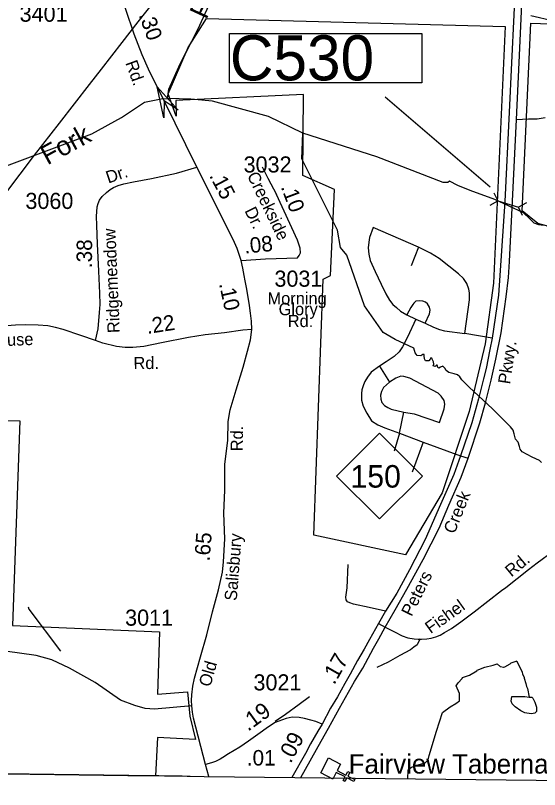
# Model space of a CAD drawing. Extents: x 1547597 to 1699558, y 810033 to 920809.
# Drawn here: x 1623103 to 1627167, y 819952 to 825959 of the extents above; entities that cross this region are included whole.
import ezdxf

# ---------------------------------------------------------------- set-up
doc = ezdxf.new("R2010")
doc.units = 0
for name, color, linetype in [('Exist Boundary Political City Limit New', 7, 'Continuous'), ('Exist Boundary Political CountyLine', 7, 'Continuous'), ('Exist Cultural Church CELL', 7, 'Continuous'), ('Exist Cultural Church Label', 7, 'Continuous'), ('Exist Hydrographic Creek Single Shore', 7, 'Continuous'), ('Exist Hydrographic Creek Single Shore Label', 7, 'Continuous'), ('Exist Hydrographic Misc Water Feature', 7, 'Continuous'), ('Exist Road Non-System Type 51', 7, 'Continuous'), ('Exist Road Primary NC Divided Attributed', 7, 'Continuous'), ('Exist Road Primary NC Label', 7, 'Continuous'), ('Exist Road Primary NC Service Mileage Hundredths English Label', 7, 'Continuous'), ('Exist Road Primary NC Shield CELL', 7, 'Continuous'), ('Exist Road Primary NC Shield Number Label', 7, 'Continuous'), ('Exist Road Primary NC Structure Culvert CELL', 7, 'Continuous'), ('Exist Road Primary NC Structure Culvert Number Label', 7, 'Continuous'), ('Exist Road Secondary Mileage Hundredths English Label', 7, 'Continuous'), ('Exist Road Secondary Structure Standard Bridge Attributed CELL', 7, 'Continuous'), ('Exist Road Secondary Type 51 Attributed', 7, 'Continuous'), ('Exist Road Secondary Type 51 Label', 7, 'Continuous'), ('Exist Road Secondary Type 51 Number Label', 7, 'Continuous'), ('Exist Utilities Electrical Transmission Line', 7, 'Continuous'), ('Map Preparation Boundary City Limit Buffer Line', 7, 'Continuous')]:
    doc.layers.add(name, color=color, linetype=linetype)

msp = doc.modelspace()

# ---------------------------------------------------------------- linework, layer by layer
at = {"layer": 'Exist Boundary Political City Limit New'}
for points in [[(1624585.1, 825934.1), (1626899.2, 825873.3), (1626810, 823882.4), (1626744.7, 823409.9), (1626621.2, 822886.4), (1626410.5, 822253.9), (1626127.2, 821774), (1625415.4, 821926.7), (1625488, 823911.5), (1625546.1, 823940.6), (1625577.9, 824608.7), (1625332.2, 824717.2), (1625335.8, 825346.1), (1624345.6, 825299.1), (1624349.2, 825176.2), (1624287.8, 825349.7), (1624443.2, 825711.2), (1624585.1, 825934.1)], [(1627100, 825900), (1628206.7, 825861), (1628172.5, 825115), (1628265.2, 825110.1), (1628245.7, 824047.1), (1627631.4, 824276.3), (1627607, 824183.6), (1627548.5, 824212.9), (1627524.2, 824247), (1627480.3, 824266.5), (1627455.9, 824271.4), (1627455.9, 824242.2), (1627441.3, 824217.8), (1627353.5, 824271.4), (1627324.3, 824266.5), (1627221.9, 824325.1), (1627153.7, 824344.6), (1627031.8, 824442.1), (1627100, 825900)], [(1622237.9, 822828.2), (1623135.5, 822813.7), (1623080, 821224.5), (1624219.3, 821176.2), (1624203.5, 820692.6), (1624436.5, 820710.6), (1624454.3, 820520.6), (1624498.1, 820339.4), (1624204.6, 820355.8), (1624188.1, 820058.9)], [(1624188.1, 820058.9), (1623982.5, 820061.2), (1621271.1, 820096.9)]]:
    msp.add_lwpolyline(points, dxfattribs=at)
at = {"layer": 'Exist Boundary Political CountyLine'}
msp.add_lwpolyline([(1606492.6, 820282.1), (1613860.9, 820194.5), (1614148.1, 820194.4), (1614278.7, 820193.7), (1614685.6, 820195), (1614832.4, 820191.9), (1615113.9, 820191.3), (1615321.1, 820189.2), (1615424.8, 820185.5), (1615839, 820171.5), (1623973.3, 820060), (1623995.2, 820060.7), (1624042.9, 820061.2), (1624114.1, 820060.5), (1624171.2, 820059.7), (1624213.4, 820059.1), (1624257.5, 820058.7), (1624364.8, 820057.3), (1624394.8, 820056.9), (1624433.9, 820056.2), (1624457.5, 820055.9), (1624566.7, 820052.4), (1633697.6, 819951.5)], dxfattribs=at)
at = {"layer": 'Exist Cultural Church CELL'}
msp.add_lwpolyline([(1625624.1, 820149.1), (1625598.1, 820098.4), (1625665.9, 820063.6), (1625680.5, 820092.1), (1625694.7, 820084.8), (1625680.1, 820056.3), (1625733.6, 820028.8), (1625726.2, 820014.6), (1625672.7, 820042), (1625658.1, 820013.6), (1625643.9, 820020.9), (1625658.5, 820049.3), (1625590.8, 820084.1), (1625564.4, 820032.9), (1625469.7, 820081.6), (1625529.4, 820197.7)], close=True, dxfattribs=at)
at = {"layer": 'Exist Hydrographic Creek Single Shore'}
for points in [[(1624282.5, 825315.4), (1624291.3, 825386.3), (1624378.8, 825583.4), (1624516.2, 825850.3), (1624895.5, 826674.4), (1624999.6, 826883.7), (1625072.7, 827054.3), (1625138.1, 827162.8), (1625227.8, 827231.5), (1625348.7, 827304.6), (1625502.5, 827438.6), (1625607.7, 827471.8), (1625689.6, 827475.1), (1625834.7, 827440.8)], [(1622087.2, 824423.2), (1622278.3, 824509.2), (1623695.3, 825040.7), (1623925.8, 825167), (1624104.2, 825285.5), (1624233.3, 825311.9), (1624282.5, 825315.4)], [(1625330.5, 825045.8), (1625066.2, 825173.5), (1624631.4, 825294.3), (1624461.9, 825309.9), (1624282.5, 825315.4)], [(1627182.1, 822488.9), (1627165.5, 822505.5), (1627110.6, 822531.5), (1627032.6, 822572.5), (1627017, 822593.5), (1627010.4, 822614.6), (1627001, 822647.8), (1626979.4, 822669.4), (1626970, 822710.9), (1626962.8, 822739.2), (1626942.8, 822767.4), (1626864.8, 822844.4), (1626802.2, 822905.3), (1626622.2, 823074.2), (1626564.6, 823131.3), (1626548, 823154.5), (1626531.4, 823169.5), (1626504.2, 823177.8), (1626464.4, 823187.8), (1626443.3, 823202.2), (1626433.4, 823222.6), (1626416.7, 823236.5), (1626399, 823229.3), (1626385.2, 823221.5), (1626379.1, 823227.6), (1626374.1, 823245.9), (1626366.9, 823244.8), (1626356.4, 823234.8), (1626340.9, 823239.8), (1626348.1, 823252), (1626345.3, 823270.3), (1626333.7, 823290.2), (1626331.5, 823299.1), (1626322.6, 823300.7), (1626317.6, 823290.2), (1626307.7, 823279.1), (1626281.6, 823279.7), (1626275.5, 823293), (1626271.1, 823316.2), (1626272.2, 823328.4), (1626262.2, 823328.4), (1626245.6, 823316.2), (1626219, 823319), (1626203, 823340.6), (1626190.8, 823377.7), (1626047.9, 823444.7), (1625953.8, 823497.3), (1625809.8, 823704.1), (1625672.8, 824097.5), (1625623.8, 824157.6), (1625600.7, 824292.6), (1625324.7, 824846.4), (1625330.5, 825045.8)], [(1627194.3, 824329.7), (1627162.7, 824333.5), (1627126.1, 824346.8), (1627090.1, 824383.9), (1627041.4, 824426.6), (1626819.9, 824531.8), (1626628.3, 824599.3), (1626534.1, 824639.2), (1626469.9, 824672.4), (1626455.5, 824663.6), (1626419, 824663.6), (1625905.3, 824861.4), (1625330.5, 825045.8)], [(1623199.8, 821369.5), (1623206.7, 821351.4), (1623453.1, 821025.6)]]:
    msp.add_lwpolyline(points, dxfattribs=at)
at = {"layer": 'Exist Hydrographic Misc Water Feature'}
for points in [[(1626990.6, 820946.9), (1626944.3, 820931), (1626936.2, 820923.1), (1626895.8, 820899.9), (1626887.7, 820898), (1626863.9, 820904.5), (1626837.3, 820926.1)], [(1626990.6, 820946.9), (1627031.2, 820863.5), (1627035, 820847.5), (1627046.6, 820823.3), (1627046.5, 820815.3), (1627061.7, 820775), (1627065.3, 820751), (1627073.1, 820734.9), (1627086.8, 820668.4)], [(1626144.9, 820032.7), (1626148.1, 820103.7), (1626172.8, 820125.5), (1626232.5, 820144.4), (1626279, 820157.5), (1626302.3, 820180.8), (1626309.8, 820215), (1626367.8, 820404.4), (1626413.7, 820548), (1626474.8, 820593.8), (1626517.6, 820618.2), (1626545.1, 820639.6), (1626545.1, 820697.7), (1626519.4, 820756.7), (1626535.8, 820780.4), (1626566.3, 820811.9), (1626570.4, 820819.8), (1626622.7, 820838.8), (1626680.6, 820873.1), (1626683.4, 820877.7), (1626743.8, 820900.6), (1626808.1, 820915.5), (1626837.3, 820926.1)], [(1627086.8, 820668.4), (1627108, 820668.3), (1627115.9, 820660.2), (1627131.3, 820629.9), (1627142.7, 820589.8), (1627142.1, 820557.8), (1627129.9, 820544.1), (1627117.8, 820540.3), (1627101.8, 820538.6), (1627053.9, 820547.4), (1627022.2, 820561.9), (1626978.7, 820592.7), (1626955.1, 820617.1), (1626947.4, 820637.2), (1626951, 820672.8), (1626964, 820672.9), (1627052.1, 820673.3), (1627086.8, 820668.4)]]:
    msp.add_lwpolyline(points, dxfattribs=at)
at = {"layer": 'Exist Road Non-System Type 51'}
for p, q in [((1626228.3, 824160.6), (1625877, 824313.2)), ((1626228.3, 824160.6), (1626172.2, 824015.8)), ((1626138.5, 823634.2), (1626208.1, 823601.1)), ((1626208.1, 823601.1), (1626278.8, 823571.9)), ((1626799.5, 823454.6), (1626586.3, 823489.4)), ((1625925.3, 823235.8), (1626002.7, 823113.5)), ((1626080.2, 822717.9), (1626113.8, 822880.6)), ((1626080.2, 822717.9), (1626039.8, 822576.5)), ((1626080.2, 822717.9), (1626265.3, 822647.2)), ((1626265.3, 822647.2), (1626178.9, 822413.7)), ((1626265.3, 822647.2), (1626554.6, 822542)), ((1626554.6, 822542), (1626613.9, 822523.8))]:
    msp.add_line(p, q, dxfattribs=at)
for points in [[(1626989.2, 825152.1), (1627082.3, 825155.4), (1627149.7, 825156.6), (1627211.4, 825167.8)], [(1625015, 824784), (1625061, 824697.1), (1625127, 824568.9)], [(1625877, 824313.2), (1625849, 824234.6), (1625842.2, 824198.7), (1625836.6, 824156.1), (1625842.2, 824106.7), (1625854.6, 824057.3), (1625891.6, 823970.9), (1625937.6, 823874.4), (1625974.7, 823798.1), (1626002.7, 823748.7), (1626029.7, 823716.1), (1626057.7, 823692.6), (1626089.1, 823664.5), (1626138.5, 823634.2)], [(1626586.3, 823489.4), (1626624.5, 823752.6), (1626624.5, 823805.4), (1626618.8, 823835.7), (1626603.1, 823878.3), (1626578.4, 823918.7), (1626538, 823953.5), (1626388.8, 824071.9), (1626321.4, 824114.5), (1626228.3, 824160.6)], [(1626278.8, 823571.9), (1626312.5, 823642.6), (1626318.1, 823672.9), (1626312.5, 823694.3), (1626297.9, 823720.1), (1626282.2, 823734.7), (1626260.8, 823741.4), (1626238.4, 823743.6), (1626208.1, 823740.3), (1626192.4, 823725.7), (1626183.4, 823716.7), (1626167.7, 823692), (1626138.5, 823634.2)], [(1626208.1, 823601.1), (1626141.9, 823463.1), (1626104.8, 823386.8), (1626077.9, 823348.6), (1626038.6, 823311.6), (1625976.9, 823269.5), (1625925.3, 823235.8)], [(1626278.8, 823571.9), (1626343.9, 823539.4), (1626392.1, 823522.5), (1626429.2, 823512.4), (1626586.3, 823489.4)], [(1625925.3, 823235.8), (1625862.4, 823189.8), (1625832.1, 823152.8), (1625810.8, 823119.1), (1625800.7, 823091), (1625789.5, 823054), (1625786.1, 823023.7), (1625786.1, 822974.3), (1625799.6, 822926.6), (1625826.5, 822872.8), (1625864.7, 822813.3)], [(1626002.7, 823113.5), (1625956.7, 823072.5), (1625941, 823041.1), (1625934.3, 823010.8), (1625935.4, 822980.5), (1625944.4, 822955.8), (1625965.7, 822931.1), (1625990.4, 822915.4), (1626015.1, 822903.1), (1626113.8, 822880.6)], [(1626392.1, 822798.7), (1626428.1, 822905.9), (1626433.7, 822941.8), (1626428.1, 822969.8), (1626403.4, 823003.5), (1626382, 823028.2), (1626159.8, 823142.7), (1626115, 823157.2), (1626091.4, 823158.4), (1626053.2, 823144.9), (1626002.7, 823113.5)], [(1626113.8, 822880.6), (1626193.5, 822866), (1626392.1, 822798.7)], [(1625864.7, 822813.3), (1625912.9, 822781.8), (1625966.8, 822758.3), (1626080.2, 822717.9)], [(1625972.1, 821335.4), (1625844.6, 821365.3), (1625724, 821391.2), (1625694.9, 821400.4), (1625678.1, 821408), (1625667.4, 821423.3), (1625664.4, 821443.2), (1625674.3, 821518), (1625683.5, 821698.3)], [(1626242.2, 821121.2), (1626223.1, 821086.1), (1626216.8, 821073.8), (1626192.8, 821055.4), (1626167.2, 821036.1), (1626084.4, 820991.3), (1625991.8, 820940.8), (1625905.1, 820898.1)], [(1624469.1, 820601.6), (1624180.2, 820574.4), (1624108.3, 820581.1), (1624027.5, 820603.5), (1623917.6, 820646.2), (1623720, 820783.1), (1623522.5, 820893.1), (1623383.4, 820958.2), (1623262.2, 820991.8), (1623022, 821025.5)], [(1625116.6, 820482.5), (1625197.6, 820535.3), (1625303.2, 820614.2), (1625383.8, 820673.8)]]:
    msp.add_lwpolyline(points, dxfattribs=at)
at = {"layer": 'Exist Road Primary NC Divided Attributed'}
for points in [[(1627021.5, 827250.3), (1627004.3, 826710.9), (1626949.5, 825591.7), (1626930.1, 825208), (1626896.9, 824515.2), (1626847.6, 823786.9), (1626799.5, 823454.6), (1626782.2, 823366.1), (1626752.3, 823218.8), (1626731.8, 823139.6), (1626693.1, 822983.4), (1626642.1, 822797.9), (1626554.6, 822542), (1626503.1, 822395.3), (1626400.1, 822164.4), (1626279.4, 821891.9), (1626157.6, 821657.1), (1626059, 821474.4), (1625972.1, 821335.4), (1625918.3, 821239.5)], [(1625969.8, 821210.2), (1626046.3, 821344.8), (1626138.2, 821507.6), (1626265, 821737.4), (1626388, 821979.4), (1626463.8, 822159.4), (1626559.1, 822375.4), (1626613.9, 822523.8), (1626703.1, 822796.2), (1626747.9, 822953), (1626792.8, 823129.1), (1626828.2, 823290.2), (1626868.1, 823494.6), (1626907.4, 823776.4), (1626926.2, 823925.4), (1626935.1, 824050), (1626956.7, 824516.8), (1626989.2, 825152.1), (1627009.8, 825594.5), (1627038.6, 826219.7), (1627059.1, 826636.7), (1627088.5, 827252)], [(1625918.3, 821239.5), (1625849.1, 821114.9), (1625806.5, 821040.2), (1625756.1, 820951.6), (1625697.4, 820848), (1625656.4, 820775.5), (1625599.4, 820671.4), (1625546.8, 820582.8), (1625480.9, 820458.2)], [(1625530.7, 820427.7), (1625616, 820583.3), (1625730.6, 820790.4), (1625797, 820892.1), (1625878.5, 821047.4), (1625920, 821120.5), (1625969.8, 821210.2)], [(1625480.9, 820458.2), (1625448.7, 820403.3), (1625391.1, 820306.4), (1625351.8, 820231.7), (1625246.6, 820044.8)], [(1625314.4, 820044.1), (1625473.7, 820326.9), (1625530.7, 820427.7)]]:
    msp.add_lwpolyline(points, dxfattribs=at)
at = {"layer": 'Exist Road Primary NC Shield CELL'}
msp.add_lwpolyline([(1625592, 822384.2), (1625925, 822717.2), (1626258, 822384.2), (1625925, 822051.2)], close=True, dxfattribs=at)
at = {"layer": 'Exist Road Primary NC Structure Culvert CELL'}
for p, q in [((1626813.7, 824583.5), (1626844.6, 824520.3)), ((1626783.2, 824486), (1626844.6, 824520.3)), ((1626844.6, 824520.3), (1627004.6, 824470.1)), ((1627066, 824504.4), (1627004.6, 824470.1)), ((1627035.4, 824406.9), (1627004.6, 824470.1))]:
    msp.add_line(p, q, dxfattribs=at)
at = {"layer": 'Exist Road Primary NC Structure Culvert Number Label'}
msp.add_line((1626784.5, 824625.9), (1625969.3, 825325.9), dxfattribs=at)
msp.add_lwpolyline([(1624762, 825819.1), (1626255.1, 825819.1), (1626255.1, 825435.3), (1624762, 825435.3)], close=True, dxfattribs=at)
at = {"layer": 'Exist Road Secondary Structure Standard Bridge Attributed CELL'}
msp.add_lwpolyline([(1624252.5, 825165.6), (1624201.5, 825404), (1624364.9, 825223), (1624257, 825295.5)], close=True, dxfattribs=at)
at = {"layer": 'Exist Road Secondary Type 51 Attributed'}
for points in [[(1624257, 825295.5), (1624135.2, 825541.3), (1624084.2, 825652.1), (1624022.2, 825814.9), (1623958, 826004.3), (1623845, 826329.9)], [(1624509.5, 824782.1), (1624257, 825295.5)], [(1623723.1, 823436.4), (1623744.7, 823526.7), (1623755.3, 823654.6), (1623759.1, 823715.5), (1623758, 823804.7), (1623748.1, 823974.7), (1623739.8, 824186.2), (1623732.6, 824329.1), (1623731.5, 824402.2), (1623733.1, 824434.3), (1623737, 824474.7), (1623743.6, 824500.2), (1623754.2, 824526.2), (1623774.1, 824555), (1623807.3, 824586.1), (1623837.8, 824608.8), (1623863.3, 824623.7), (1623899.8, 824640.3), (1623944.1, 824653.1), (1624016.9, 824667.6), (1624157.1, 824693.3), (1624351.6, 824734.4), (1624509.5, 824782.1)], [(1624854, 824057.2), (1624822.4, 824149.7), (1624802.5, 824195.6), (1624764.8, 824271.5), (1624701.7, 824398.3), (1624624.7, 824552.3), (1624509.5, 824782.1)], [(1625290.9, 824077.7), (1625302.5, 824096), (1625312, 824117.6), (1625310.3, 824154.1), (1625290.4, 824214.5), (1625127, 824568.9)], [(1624854, 824057.2), (1625042.8, 824071), (1625290.9, 824077.7)], [(1624934.8, 823522.8), (1624933.2, 823585.9), (1624926.6, 823649.5), (1624918, 823707.8), (1624896.1, 823834), (1624885, 823898.3), (1624877.2, 823941.5), (1624866.7, 823998.5), (1624854, 824057.2)], [(1623723.1, 823436.4), (1623610.2, 823474.6), (1623473.4, 823521.1), (1623413.6, 823538.3), (1623352.7, 823550.5), (1623279.6, 823554.9), (1623177.7, 823557.7), (1623102.9, 823554.9), (1622929, 823541.1)], [(1624934.8, 823522.8), (1624866.4, 823516), (1624723, 823495.8), (1624572.8, 823479.7), (1624444.8, 823460.2), (1624234.8, 823417.9), (1624098.5, 823390.3), (1624011.8, 823382.9), (1623952.4, 823382.7), (1623884.9, 823389.9), (1623779.1, 823415.4), (1623723.1, 823436.4)], [(1624576.4, 820146.4), (1624484, 820506.3), (1624476.3, 820551.7), (1624469.1, 820601.6), (1624467.4, 820642.6), (1624469.1, 820686.9), (1624478.5, 820753.3), (1624490.7, 820815.9), (1624538.3, 820980.9), (1624585.9, 821153.2), (1624630.8, 821330.9), (1624676.2, 821502.5), (1624707.6, 821639.4), (1624716.6, 821717.9), (1624725.6, 821897.5), (1624717.8, 822097.3), (1624726.4, 822275.1), (1624727.5, 822476.9), (1624748.7, 822660.6), (1624750.9, 822808.4), (1624768.2, 822898.6), (1624813.1, 823053.4), (1624869.2, 823228.5), (1624902.7, 823354.4), (1624924.3, 823441.9), (1624934.8, 823522.8)], [(1625969.8, 821210.2), (1626041.9, 821174.9), (1626102.2, 821145.4), (1626145.9, 821129.3), (1626193.6, 821121), (1626225.1, 821117.7), (1626251.7, 821118.8), (1626292.1, 821120.5), (1626327.6, 821125.5), (1626362.5, 821136), (1626395.7, 821149.3), (1626431.1, 821169.2), (1626484.3, 821201.3), (1626556.9, 821252.8), (1626658.8, 821330.9), (1626871.4, 821495.9), (1626904.6, 821520.3), (1627080.7, 821658.8), (1627147.9, 821710.2), (1627274.6, 821804.4)], [(1625918.3, 821239.5), (1625969.8, 821210.2)], [(1625480.9, 820458.2), (1625431.1, 820479.3), (1625392.6, 820489.8), (1625343.5, 820503.8), (1625301.5, 820510.8), (1625247.2, 820512.6), (1625201.1, 820501.9), (1625116.6, 820471.6), (1625065.7, 820438.1), (1624982.9, 820377.6), (1624909.7, 820327.8), (1624842.1, 820280.2), (1624754.7, 820228.1), (1624710.1, 820199.3), (1624690.2, 820187.1), (1624675.1, 820180), (1624652.8, 820168.5), (1624622.9, 820159.2), (1624576.4, 820146.4)], [(1624601.5, 820052), (1624576.4, 820146.4)]]:
    msp.add_lwpolyline(points, dxfattribs=at)
at = {"layer": 'Exist Utilities Electrical Transmission Line'}
for points in [[(1619633.6, 820115.5), (1620615.1, 821395.4), (1620681.2, 821494.4), (1620852.6, 821717.7), (1620958.6, 821864), (1621075, 822018.1), (1621364.8, 822393.5), (1621626.1, 822747.2), (1621891.2, 823093), (1622184.9, 823474.2), (1622458.6, 823845.7), (1622741.9, 824209.2), (1623027.6, 824580.6), (1623249.9, 824875), (1623443.6, 825123.8), (1623676.2, 825422.1), (1623770.1, 825542.7), (1623929.2, 825748.2), (1624053.5, 825908.1), (1624292.2, 826212.2)], [(1627099.3, 825959.2), (1627278.6, 825916.3)]]:
    msp.add_lwpolyline(points, dxfattribs=at)
at = {"layer": 'Map Preparation Boundary City Limit Buffer Line'}
for points in [[(1624585.1, 825934.1), (1626899.2, 825873.3), (1626810, 823882.4), (1626744.7, 823409.9), (1626621.2, 822886.4), (1626410.5, 822253.9), (1626127.2, 821774), (1625415.4, 821926.7), (1625488, 823911.5), (1625546.1, 823940.6), (1625577.9, 824608.7), (1625332.2, 824717.2), (1625335.8, 825346.1), (1624345.6, 825299.1), (1624349.2, 825176.2), (1624287.8, 825349.7), (1624443.2, 825711.2), (1624585.1, 825934.1)], [(1627100, 825900), (1628206.7, 825861), (1628172.5, 825115), (1628265.2, 825110.1), (1628245.7, 824047.1), (1627631.4, 824276.3), (1627607, 824183.6), (1627548.5, 824212.9), (1627524.2, 824247), (1627480.3, 824266.5), (1627455.9, 824271.4), (1627455.9, 824242.2), (1627441.3, 824217.8), (1627353.5, 824271.4), (1627324.3, 824266.5), (1627221.9, 824325.1), (1627153.7, 824344.6), (1627031.8, 824442.1), (1627100, 825900)], [(1622237.9, 822828.2), (1623135.5, 822813.7), (1623080, 821224.5), (1624219.3, 821176.2), (1624203.5, 820692.6), (1624436.5, 820710.6), (1624454.3, 820520.6), (1624498.1, 820339.4), (1624204.6, 820355.8), (1624188.1, 820058.9)], [(1624188.1, 820058.9), (1623982.5, 820061.2), (1621271.1, 820096.9)]]:
    msp.add_lwpolyline(points, dxfattribs=at)

# ---------------------------------------------------------------- texts
at = {"layer": 'Exist Cultural Church Label'}
msp.add_text('Fairview Tabernacle', height=150, dxfattribs=at).set_placement((1625686.9, 820075.2))
at = {"layer": 'Exist Hydrographic Creek Single Shore Label'}
for s, rotation, p in [('Fiddler', 65.12101, (1624583, 825921.7)), ('Fork', 28.77468, (1623350.1, 824795))]:
    msp.add_text(s, height=150, rotation=rotation, dxfattribs=at).set_placement(p)
at = {"layer": 'Exist Road Primary NC Label'}
for s, rotation, p in [('Pkwy.', 81.22468, (1626937.8, 823093.3)), ('Creek', 68.17131, (1626507, 821929.9)), ('Peters', 63.56008, (1626174.8, 821288.7))]:
    msp.add_text(s, height=95, rotation=rotation, dxfattribs=at).set_placement(p)
at = {"layer": 'Exist Road Primary NC Service Mileage Hundredths English Label'}
for s, rotation, p in [('.17', 60.45349, (1625574.8, 820758.6)), ('.09', 62.25895, (1625237.4, 820148.3))]:
    msp.add_text(s, height=125, rotation=rotation, dxfattribs=at).set_placement(p)
at = {"layer": 'Exist Road Primary NC Shield Number Label'}
msp.add_text('150', height=175, dxfattribs=at).set_placement((1625701.1, 822294.5))
at = {"layer": 'Exist Road Primary NC Structure Culvert Number Label'}
msp.add_text('C530', height=350, dxfattribs=at).set_placement((1624765.3, 825455))
at = {"layer": 'Exist Road Secondary Mileage Hundredths English Label'}
for s, height, rotation, p in [('.30', 120, 289.83506, (1624057.3, 825962.8)), ('.15', 120, 297.92413, (1624602.8, 824715.9)), ('.10', 120, 290.67923, (1625158.9, 824628)), ('.08', 120, 5.61513, (1624881.2, 824110.1)), ('.38', 120, 89.37892, (1623695.2, 823997.6)), ('.10', 120, 282.30299, (1624680.6, 823876.3)), ('.22', 120, 8.61037, (1624125.4, 823486.6)), ('.65', 120, 85.62264, (1624608.3, 821720.6)), ('.19', 125, 36.17965, (1624906.3, 820399))]:
    msp.add_text(s, height=height, rotation=rotation, dxfattribs=at).set_placement(p)
msp.add_text('.01', height=120, dxfattribs=at).set_placement((1624896.8, 820137.9))
at = {"layer": 'Exist Road Secondary Type 51 Label'}
for s, rotation, p in [('Rd.', 290.00142, (1623953.7, 825590.7)), ('Dr.', 18.61487, (1623822.6, 824654.1)), ('Creekside', 295.84439, (1624896.4, 824718)), ('Dr.', 296.11391, (1624876.9, 824444.2)), ('Ridgemeadow', 92.48708, (1623912.5, 823496.1)), ('Greenhouse', 2.32489, (1622544.8, 823373.3)), ('Rd.', 0.42455, (1624018.1, 823213.7)), ('Rd.', 89.14815, (1624865.4, 822575.9)), ('Salisbury', 85.62264, (1624818.4, 821413.6)), ('Rd.', 39.68189, (1626948.8, 821596.4)), ('Fishel', 35.60729, (1626322, 821157.4)), ('Old', 74.09215, (1624613.2, 820742.4))]:
    msp.add_text(s, height=95, rotation=rotation, dxfattribs=at).set_placement(p)
for s, p in [('Morning', (1625057.3, 823715.9)), ('Glory', (1625143.4, 823632.5)), ('Rd.', (1625214.3, 823540.2))]:
    msp.add_text(s, height=95, dxfattribs=at).set_placement(p)
at = {"layer": 'Exist Road Secondary Type 51 Number Label'}
for s, p in [('3401', (1623134.7, 825910.1)), ('3032', (1624871.8, 824740.1)), ('3060', (1623179.6, 824457.1)), ('3031', (1625110.9, 823853.6)), ('3011', (1623952.9, 821222.9)), ('3021', (1624948.3, 820720.5))]:
    msp.add_text(s, height=125, dxfattribs=at).set_placement(p)

doc.saveas('drawing.dxf')
